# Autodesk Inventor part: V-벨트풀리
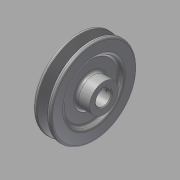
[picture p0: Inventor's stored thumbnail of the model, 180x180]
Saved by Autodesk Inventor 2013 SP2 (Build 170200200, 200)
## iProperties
Created: 2015-09
Part Number: V-벨트풀리
Material: 강철, 연강
Document SubType Name: Modeling
Designer: mduedu
Density: 7.86 g/cm^3
Mass: 779.014 g
Surface Area: 277.465 cm^2
Volume: 99.1112 cm^3
Author: mduedu
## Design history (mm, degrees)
sketch "스케치1"
  geometry: L1 (-10, 0)-(10, 0); L2 (-10, 0)-(-10, 48); L3 (-10, 48)-(-5.976, 48); L4 (-5.976, 48)-(-2.154, 35.5); L5 (-2.154, 35.5)-(2.154, 35.5); L6 (2.154, 35.5)-(5.976, 48); L7 (5.976, 48)-(10, 48); L8 (10, 48)-(10, 0); L9 (0, 0)-(0, 35.5); L10 (-10, 43.5)-(10, 43.5); 3 further points
  constraints: 20 end point, 6 point on line, 3 perpendicular, 2 midpoint, 2 parallel, 2 symmetric about line, 1 coincident, 1 collinear, 1 equal length, 1 horizontal, 1 vertical, 1 vertical alignment
  dimensions: "d0" = 20 distance between parallel lines of L8 L2; "d2" = 96 diameter of L3 L1; "d3" = 87 diameter of L10 L1; "d4" = 4.5 distance between parallel lines of L10 L3 (derived); "d5" = 8 distance between parallel lines of L5 L10; "d6" = 9.2 distance of point (4.6, 43.5) point (-4.6, 43.5); "d7" = 34 deg angle of L6 L4
revolve "회전1" sketch "스케치1" stored, may be unused: angle "d8" = 90 deg
sketch "스케치2"
  geometry: C1 r 16 at (0, 0); 1 further point
  constraints: 1 centre point, 1 coincident
  dimensions: "d9" = 32 diameter of C1
extrude "돌출1" join sketch "스케치2" distance "d10" = 11; taper "d11" = 0 deg
fillet "모깎기1" dims "d12" = 1, "d13" = 0.5, "d14" = 2
sketch "스케치3"
  geometry: C1 r 16 at (0, 0) reference; C2 r 32 at (0, 0); 1 further point
  constraints: 1 centre point, 1 coincident
  dimensions: "d15" = 64 diameter of C2
extrude "돌출2" cut sketch "스케치3" distance "d16" = 4; taper "d17" = 0 deg
fillet "모깎기2" dims "d18" = 3
fillet "모깎기3" dims "d19" = 3
fillet "모깎기4" dims "d20" = 3
sketch "스케치4"
  geometry: C1 r 8.5 at (0, 0); 1 further point
  constraints: 1 centre point, 1 coincident
  dimensions: "d21" = 17 diameter of C1
extrude "돌출3" cut sketch "스케치4" stored distance "d22" = 4; taper "d23" = 0 deg
sketch "스케치5"
  geometry: L1 (-2.5, 8.124)-(2.5, 8.124); L2 (2.5, 8.124)-(2.5, 10.8); L3 (2.5, 10.8)-(-2.5, 10.8); L4 (-2.5, 10.8)-(-2.5, 8.124); A1 r 8.5 centre (0, 0) between (-2.5, 8.124) and (2.5, 8.124) reference; 2 further points
  constraints: 8 end point, 3 point on circle, 2 parallel, 1 horizontal, 1 perpendicular, 1 vertical alignment
  dimensions: "d24" = 5 distance of L2.end L3.end; "d26" = 19.3 distance from line of L3 point (0, -8.5)
extrude "돌출4" cut sketch "스케치5" stored distance "d27" = 4; taper "d28" = 0 deg
chamfer "모따기1" distance "d29" = 1; stored, may be unused: second distance "d30" = 2, angle "d31" = 45 deg
node "작업 평면1"
sketch "스케치6"
  geometry: L1 (-11, 16)-(-11, -16) reference; 2 further points
  constraints: 1 horizontal alignment
  dimensions: "d32" = 5 distance from line of point (-6, 0) L1
hole "구멍1" sketch "스케치6" at (-6, 0) diameter "d33" = 3.242; stored, may be unused: countersink angle "d37" = 90 deg, drill point angle "d39" = 118 deg; dims "d34" = 6, "d35" = 4, "d36" = 2, "d38" = 8
node "솔리드1"
mirror "대칭1"
